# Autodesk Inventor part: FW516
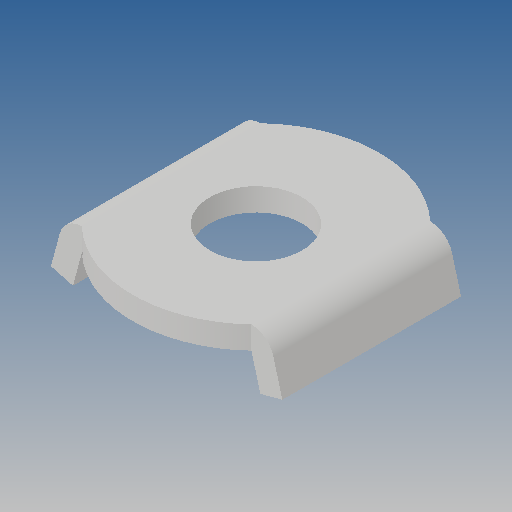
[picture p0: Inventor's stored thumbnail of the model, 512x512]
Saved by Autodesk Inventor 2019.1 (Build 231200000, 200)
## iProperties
Created: 2015-08
Part Number: FW516
Material: Ogólny
Document SubType Name: Modeling
Designer: CADENGINEERING4
Density: 1 g/cm^3
Appearance: Domyślna
Author: CADENGINEERING4
Revision Number: ÈÎºÎ
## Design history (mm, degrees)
feature "ÇÐ³ý-À­Éì4"
node "Bryła1"
